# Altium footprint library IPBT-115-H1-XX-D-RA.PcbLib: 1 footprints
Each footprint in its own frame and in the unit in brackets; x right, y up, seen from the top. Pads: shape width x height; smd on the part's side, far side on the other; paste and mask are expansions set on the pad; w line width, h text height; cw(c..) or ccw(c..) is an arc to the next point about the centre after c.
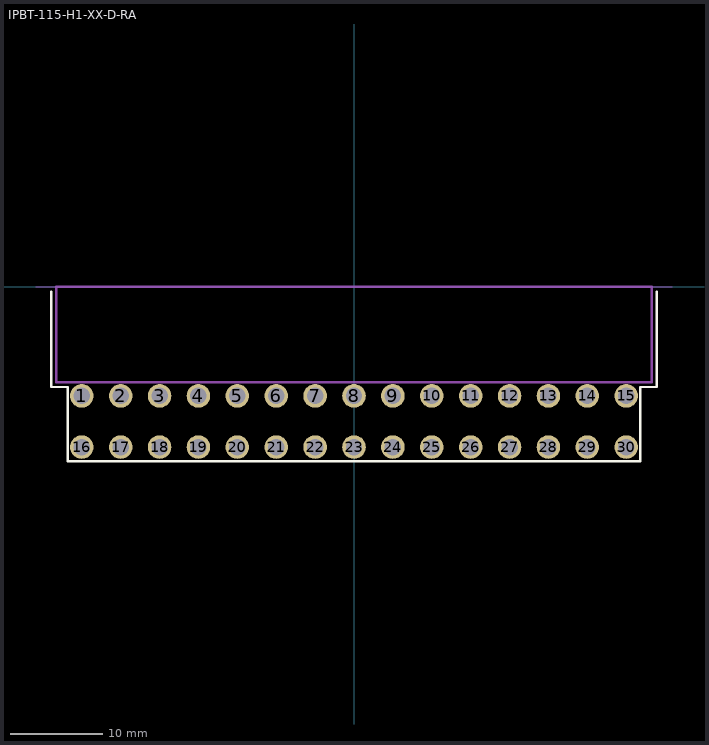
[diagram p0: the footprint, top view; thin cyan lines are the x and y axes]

## IPBT-115-H1-XX-D-RA [mil]
pads (30):
  round 100 hole 70 mask+3: 1(-1155,-463) 2(-990,-463) 3(-825,-463) 4(-660,-463) 5(-495,-463) 6(-330,-463) 7(-165,-463) 8(0,-463) 9(165,-463) 10(330,-463) 11(495,-463) 12(660,-463) 13(825,-463) 14(990,-463) 15(1155,-463) 16(-1155,-680) 17(-990,-680) 18(-825,-680) 19(-660,-680) 20(-495,-680) 21(-330,-680) 22(-165,-680) 23(0,-680) 24(165,-680) 25(330,-680) 26(495,-680) 27(660,-680) 28(825,-680) 29(990,-680) 30(1155,-680)
Top Overlay:
  lines w10: -1284,-20 -1284,-425 -1215,-425 -1215,-740 1215,-740 1215,-425 1284,-425 1284,-20
Mechanical 1:
  lines w10: -1264,-405 -1264,0 1264,0 1264,-405 -1264,-405
  text "J1" at -17.57,-218.84 h30
Mechanical 16:
  lines w0.1: -1350,0 1350,0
